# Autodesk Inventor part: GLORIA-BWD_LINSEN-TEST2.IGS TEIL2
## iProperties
Created: 2005-04
Part Number: GLORIA-BWD_LINSEN-TEST2.IGS TEIL2
Document SubType Name: Modeling
Designer: Nordmeyer
Manufacturer: Standard
Standards Organization: Custom
Author: Nordmeyer
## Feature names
1. Erst1
